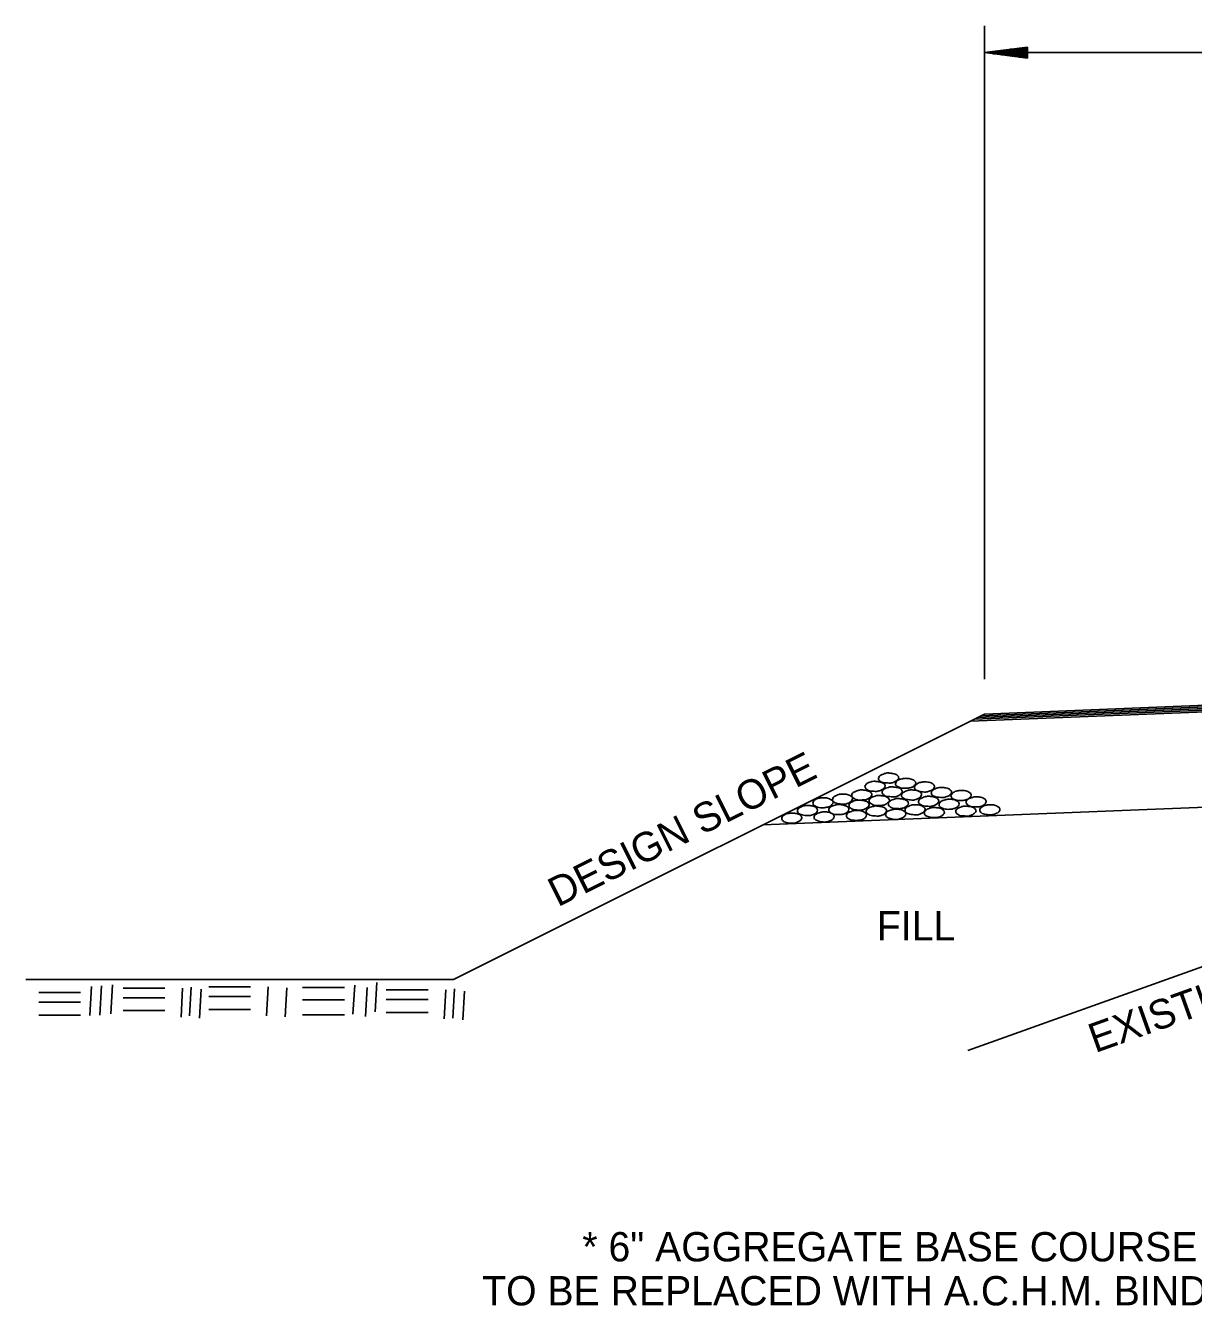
# Model space of a CAD drawing. Extents: x 836 to 5683, y -463 to 1545.
# Drawn here: x 4460.8 to 4699.8, y 626.9 to 890.5 of the extents above; entities that cross this region are included whole.
import ezdxf

# ---------------------------------------------------------------- set-up
doc = ezdxf.new("R2010")
doc.units = 0
doc.layers.add('R_Grid', color=7, linetype='Continuous')
doc.layers.add('R_No Plot', color=7, linetype='Continuous')

msp = doc.modelspace()

# ---------------------------------------------------------------- linework, layer by layer
at = {"layer": 'R_Grid'}
for p, q in [((4657.04, 756.76), (4657.04, 890.46)), ((4665.86, 886.11), (4657.04, 884.96)), ((4665.87, 885.88), (4664.13, 885.87)), ((4665.86, 886.11), (4665.87, 883.82)), ((4657.04, 884.96), (5217.98, 884.96)), ((4657.04, 884.96), (4665.87, 884.96)), ((4665.87, 883.82), (4657.04, 884.96)), ((4665.86, 885.19), (4658.83, 885.19)), ((4665.87, 884.74), (4658.84, 884.73)), ((4665.87, 885.42), (4660.56, 885.41)), ((4665.87, 884.5), (4660.57, 884.5)), ((4665.86, 885.65), (4662.34, 885.65)), ((4665.87, 884.28), (4662.35, 884.27)), ((4665.87, 884.04), (4664.14, 884.04))]:
    msp.add_line(p, q, dxfattribs=at)
at = {"layer": 'R_No Plot'}
for p, q in [((4654.18, 748.2), (5220.52, 770.79)), ((4654.91, 748.58), (5219.89, 771.11)), ((4655.64, 748.93), (5219.26, 771.42)), ((4656.39, 749.31), (5218.6, 771.74)), ((4657.04, 749.63), (5218, 772.04)), ((4548.38, 695.34), (4657.04, 749.63)), ((4611.68, 726.96), (4831.44, 735.71)), ((4782.86, 727.01), (4653.67, 680.84)), ((4460.81, 695.34), (4548.38, 695.34)), ((4474.27, 693.88), (4473.92, 687.95)), ((4476.29, 694.02), (4475.98, 688.07)), ((4478.57, 694.22), (4478.21, 688.31)), ((4480.72, 693.57), (4489.3, 693.57)), ((4492.91, 693.57), (4492.59, 687.64)), ((4494.7, 693.76), (4494.36, 687.87)), ((4496.73, 693.38), (4496.4, 687.43)), ((4498.26, 693.83), (4506.84, 693.83)), ((4510.46, 693.83), (4510.12, 687.91)), ((4514.25, 693.6), (4513.93, 687.7)), ((4517.45, 693.69), (4526.02, 693.69)), ((4528.14, 694.18), (4527.79, 688.26)), ((4530.68, 693.67), (4530.33, 687.78)), ((4532.69, 694.71), (4532.34, 688.75)), ((4548.58, 693.4), (4548.25, 687.45)), ((4463.46, 692.68), (4472.01, 692.68)), ((4463.46, 690.71), (4472.01, 690.71)), ((4480.72, 691.61), (4489.3, 691.61)), ((4498.26, 691.85), (4506.84, 691.85)), ((4517.45, 691.16), (4526.02, 691.16)), ((4534.6, 693.19), (4543.19, 693.19)), ((4534.6, 691.22), (4543.19, 691.22)), ((4546.79, 693.19), (4546.48, 687.27)), ((4550.61, 692.96), (4550.26, 687.06)), ((4463.46, 688.05), (4472.01, 688.05)), ((4480.72, 688.97), (4489.3, 688.97)), ((4498.26, 689.22), (4506.84, 689.22)), ((4517.45, 688.11), (4526.02, 688.11)), ((4534.6, 688.57), (4543.19, 688.57))]:
    msp.add_line(p, q, dxfattribs=at)
for points in [[(4634.61, 735.9), (4635.35, 735.8), (4636.19, 735.59), (4636.66, 735.18), (4636.73, 734.93), (4636.5, 734.48), (4636.23, 734.29), (4635.74, 734.03), (4635.04, 733.83), (4634.69, 733.83), (4634.15, 733.89), (4633.53, 733.93), (4633.08, 734.12), (4632.67, 734.52), (4632.59, 734.79), (4632.74, 735.19), (4633.07, 735.47), (4633.38, 735.61), (4633.86, 735.77), (4634.15, 735.87), (4634.61, 735.9)], [(4637.38, 737.59), (4638.1, 737.5), (4638.97, 737.26), (4639.43, 736.87), (4639.5, 736.61), (4639.28, 736.17), (4639, 735.97), (4638.5, 735.69), (4637.82, 735.52), (4637.45, 735.52), (4636.92, 735.58), (4636.29, 735.61), (4635.86, 735.8), (4635.43, 736.2), (4635.37, 736.47), (4635.5, 736.88), (4635.82, 737.13), (4636.13, 737.28), (4636.62, 737.45), (4636.9, 737.57), (4637.38, 737.59)], [(4640.88, 736.5), (4641.62, 736.44), (4642.48, 736.16), (4642.9, 735.78), (4642.97, 735.56), (4642.75, 735.08), (4642.54, 734.86), (4642.03, 734.61), (4641.36, 734.47), (4640.98, 734.45), (4640.44, 734.46), (4639.82, 734.56), (4639.38, 734.77), (4638.92, 735.11), (4638.85, 735.4), (4638.97, 735.78), (4639.33, 736.1), (4639.63, 736.24), (4640.13, 736.38), (4640.43, 736.44), (4640.88, 736.5)], [(4644.74, 735.75), (4645.46, 735.73), (4646.36, 735.44), (4646.77, 735.02), (4646.85, 734.77), (4646.6, 734.32), (4646.37, 734.12), (4645.89, 733.91), (4645.18, 733.71), (4644.8, 733.68), (4644.26, 733.73), (4643.67, 733.83), (4643.21, 734.01), (4642.78, 734.36), (4642.71, 734.63), (4642.85, 735.03), (4643.18, 735.29), (4643.48, 735.52), (4643.97, 735.67), (4644.28, 735.73), (4644.74, 735.75)], [(4627.99, 733.27), (4628.74, 733.22), (4629.58, 732.95), (4630.02, 732.54), (4630.06, 732.29), (4629.85, 731.86), (4629.62, 731.65), (4629.14, 731.4), (4628.44, 731.21), (4628.08, 731.21), (4627.53, 731.27), (4626.94, 731.32), (4626.47, 731.49), (4626.02, 731.88), (4625.96, 732.17), (4626.08, 732.56), (4626.41, 732.82), (4626.73, 733.01), (4627.25, 733.18), (4627.53, 733.25), (4627.99, 733.27)], [(4631.91, 734.12), (4632.64, 734.05), (4633.49, 733.78), (4633.94, 733.42), (4634, 733.15), (4633.76, 732.72), (4633.5, 732.48), (4633.06, 732.22), (4632.36, 732.07), (4632, 732.07), (4631.44, 732.05), (4630.83, 732.15), (4630.36, 732.36), (4629.93, 732.75), (4629.88, 732.99), (4630.01, 733.43), (4630.32, 733.68), (4630.66, 733.83), (4631.17, 733.99), (4631.44, 734.08), (4631.91, 734.12)], [(4635.44, 732.99), (4636.18, 732.92), (4637.06, 732.66), (4637.5, 732.27), (4637.58, 732.02), (4637.35, 731.57), (4637.11, 731.38), (4636.59, 731.08), (4635.92, 730.93), (4635.54, 730.93), (4634.99, 730.95), (4634.39, 731.01), (4633.94, 731.25), (4633.5, 731.61), (4633.44, 731.9), (4633.58, 732.29), (4633.91, 732.56), (4634.23, 732.7), (4634.69, 732.85), (4634.98, 732.95), (4635.44, 732.99)], [(4638.13, 734.76), (4638.85, 734.67), (4639.73, 734.46), (4640.15, 734.03), (4640.21, 733.79), (4640, 733.34), (4639.74, 733.14), (4639.28, 732.87), (4638.59, 732.7), (4638.21, 732.7), (4637.66, 732.75), (4637.05, 732.78), (4636.6, 732.99), (4636.17, 733.38), (4636.09, 733.65), (4636.22, 734.06), (4636.56, 734.31), (4636.89, 734.46), (4637.38, 734.64), (4637.66, 734.74), (4638.13, 734.76)], [(4642.1, 734.11), (4642.83, 734.08), (4643.72, 733.81), (4644.13, 733.39), (4644.19, 733.14), (4643.97, 732.69), (4643.76, 732.49), (4643.24, 732.25), (4642.57, 732.05), (4642.2, 732.05), (4641.63, 732.09), (4641.04, 732.19), (4640.59, 732.35), (4640.14, 732.73), (4640.08, 733.01), (4640.19, 733.42), (4640.54, 733.67), (4640.86, 733.84), (4641.35, 734.03), (4641.63, 734.1), (4642.1, 734.11)], [(4648.2, 734.62), (4648.95, 734.58), (4649.8, 734.31), (4650.22, 733.91), (4650.3, 733.64), (4650.06, 733.21), (4649.87, 733.01), (4649.35, 732.78), (4648.66, 732.56), (4648.3, 732.56), (4647.75, 732.61), (4647.17, 732.68), (4646.68, 732.85), (4646.22, 733.23), (4646.16, 733.5), (4646.29, 733.91), (4646.62, 734.17), (4646.96, 734.36), (4647.45, 734.54), (4647.75, 734.59), (4648.2, 734.62)], [(4652.26, 734.01), (4652.99, 733.99), (4653.83, 733.68), (4654.26, 733.31), (4654.33, 733.05), (4654.12, 732.58), (4653.87, 732.39), (4653.4, 732.15), (4652.69, 731.96), (4652.33, 731.93), (4651.79, 731.98), (4651.18, 732.07), (4650.71, 732.25), (4650.27, 732.61), (4650.2, 732.89), (4650.34, 733.28), (4650.66, 733.57), (4651, 733.77), (4651.49, 733.91), (4651.8, 733.99), (4652.26, 734.01)], [(4620.81, 730.93), (4621.53, 730.89), (4622.41, 730.64), (4622.83, 730.21), (4622.9, 729.97), (4622.68, 729.51), (4622.45, 729.31), (4621.96, 729.1), (4621.27, 728.88), (4620.9, 728.88), (4620.33, 728.92), (4619.73, 729.02), (4619.28, 729.17), (4618.84, 729.55), (4618.78, 729.84), (4618.9, 730.23), (4619.25, 730.5), (4619.58, 730.69), (4620.06, 730.85), (4620.33, 730.92), (4620.81, 730.93)], [(4623.97, 732.53), (4624.7, 732.49), (4625.55, 732.19), (4626, 731.83), (4626.07, 731.6), (4625.82, 731.12), (4625.61, 730.88), (4625.1, 730.67), (4624.43, 730.5), (4624.08, 730.47), (4623.5, 730.48), (4622.87, 730.6), (4622.44, 730.8), (4622, 731.15), (4621.94, 731.42), (4622.07, 731.83), (4622.39, 732.12), (4622.73, 732.27), (4623.21, 732.43), (4623.49, 732.49), (4623.97, 732.53)], [(4627.28, 731.15), (4627.98, 731.07), (4628.82, 730.8), (4629.26, 730.43), (4629.31, 730.17), (4629.12, 729.73), (4628.88, 729.48), (4628.4, 729.24), (4627.68, 729.1), (4627.32, 729.1), (4626.76, 729.11), (4626.16, 729.17), (4625.7, 729.38), (4625.27, 729.77), (4625.18, 730.05), (4625.32, 730.45), (4625.64, 730.7), (4625.99, 730.84), (4626.48, 731), (4626.78, 731.1), (4627.28, 731.15)], [(4631.35, 732.04), (4632.06, 731.99), (4632.95, 731.74), (4633.38, 731.32), (4633.44, 731.07), (4633.22, 730.63), (4633, 730.43), (4632.49, 730.18), (4631.82, 729.99), (4631.42, 729.99), (4630.87, 730.02), (4630.27, 730.11), (4629.82, 730.28), (4629.38, 730.67), (4629.31, 730.93), (4629.45, 731.34), (4629.78, 731.6), (4630.1, 731.78), (4630.59, 731.96), (4630.87, 732.02), (4631.35, 732.04)], [(4634.93, 730.84), (4635.65, 730.76), (4636.5, 730.5), (4636.92, 730.11), (4636.99, 729.88), (4636.79, 729.43), (4636.56, 729.19), (4636.07, 728.93), (4635.37, 728.78), (4634.99, 728.78), (4634.44, 728.8), (4633.86, 728.87), (4633.38, 729.1), (4632.92, 729.46), (4632.85, 729.76), (4633, 730.14), (4633.34, 730.41), (4633.66, 730.56), (4634.15, 730.7), (4634.46, 730.8), (4634.93, 730.84)], [(4639.41, 732.36), (4640.14, 732.27), (4640.98, 732.04), (4641.42, 731.63), (4641.48, 731.38), (4641.25, 730.93), (4641.04, 730.73), (4640.54, 730.47), (4639.86, 730.29), (4639.48, 730.29), (4638.94, 730.33), (4638.32, 730.38), (4637.85, 730.6), (4637.43, 730.98), (4637.36, 731.26), (4637.47, 731.64), (4637.81, 731.9), (4638.15, 732.07), (4638.66, 732.23), (4638.94, 732.34), (4639.41, 732.36)], [(4642.84, 731.1), (4643.57, 731.04), (4644.43, 730.76), (4644.84, 730.37), (4644.91, 730.11), (4644.68, 729.67), (4644.49, 729.47), (4643.99, 729.25), (4643.29, 729.02), (4642.92, 729.02), (4642.37, 729.09), (4641.77, 729.15), (4641.31, 729.31), (4640.84, 729.71), (4640.79, 729.99), (4640.92, 730.38), (4641.25, 730.65), (4641.59, 730.81), (4642.07, 731), (4642.37, 731.07), (4642.84, 731.1)], [(4645.63, 732.82), (4646.37, 732.76), (4647.2, 732.49), (4647.63, 732.1), (4647.69, 731.88), (4647.49, 731.39), (4647.25, 731.19), (4646.75, 730.92), (4646.05, 730.76), (4645.7, 730.76), (4645.16, 730.77), (4644.55, 730.84), (4644.08, 731.07), (4643.62, 731.43), (4643.55, 731.74), (4643.7, 732.12), (4644.03, 732.39), (4644.35, 732.53), (4644.84, 732.69), (4645.18, 732.79), (4645.63, 732.82)], [(4646.75, 730.5), (4647.48, 730.47), (4648.36, 730.2), (4648.78, 729.78), (4648.85, 729.53), (4648.63, 729.1), (4648.42, 728.89), (4647.91, 728.64), (4647.23, 728.46), (4646.85, 728.46), (4646.29, 728.5), (4645.68, 728.59), (4645.25, 728.74), (4644.79, 729.13), (4644.73, 729.41), (4644.86, 729.8), (4645.2, 730.06), (4645.51, 730.24), (4646, 730.44), (4646.29, 730.5), (4646.75, 730.5)], [(4649.79, 732.22), (4650.51, 732.18), (4651.38, 731.88), (4651.81, 731.51), (4651.87, 731.28), (4651.65, 730.79), (4651.44, 730.57), (4650.92, 730.34), (4650.24, 730.18), (4649.88, 730.15), (4649.33, 730.16), (4648.71, 730.27), (4648.27, 730.48), (4647.83, 730.81), (4647.75, 731.12), (4647.89, 731.51), (4648.2, 731.81), (4648.55, 731.95), (4649.03, 732.1), (4649.32, 732.18), (4649.79, 732.22)], [(4653.17, 730.81), (4653.94, 730.74), (4654.79, 730.52), (4655.24, 730.1), (4655.32, 729.87), (4655.09, 729.41), (4654.84, 729.21), (4654.32, 728.93), (4653.65, 728.76), (4653.29, 728.76), (4652.73, 728.81), (4652.11, 728.84), (4651.66, 729.07), (4651.25, 729.45), (4651.18, 729.73), (4651.31, 730.11), (4651.64, 730.38), (4651.94, 730.53), (4652.44, 730.7), (4652.73, 730.81), (4653.17, 730.81)], [(4655.37, 732.73), (4656.1, 732.65), (4656.94, 732.39), (4657.36, 731.99), (4657.42, 731.76), (4657.22, 731.3), (4656.99, 731.07), (4656.49, 730.8), (4655.78, 730.67), (4655.43, 730.67), (4654.89, 730.69), (4654.28, 730.73), (4653.8, 730.96), (4653.36, 731.34), (4653.3, 731.61), (4653.42, 732.02), (4653.76, 732.28), (4654.09, 732.43), (4654.57, 732.58), (4654.91, 732.68), (4655.37, 732.73)], [(4658.15, 731.08), (4658.87, 731.06), (4659.73, 730.75), (4660.14, 730.38), (4660.22, 730.13), (4660.01, 729.66), (4659.76, 729.46), (4659.31, 729.24), (4658.58, 729.05), (4658.23, 729.02), (4657.69, 729.07), (4657.07, 729.17), (4656.6, 729.33), (4656.16, 729.7), (4656.1, 729.97), (4656.23, 730.37), (4656.55, 730.67), (4656.89, 730.84), (4657.39, 731), (4657.69, 731.06), (4658.15, 731.08)], [(4617.57, 729.38), (4618.34, 729.31), (4619.18, 729.07), (4619.6, 728.64), (4619.67, 728.42), (4619.45, 727.96), (4619.24, 727.77), (4618.73, 727.53), (4618.04, 727.31), (4617.67, 727.31), (4617.12, 727.35), (4616.53, 727.42), (4616.07, 727.62), (4615.62, 727.98), (4615.55, 728.27), (4615.69, 728.66), (4616, 728.93), (4616.33, 729.13), (4616.84, 729.29), (4617.12, 729.35), (4617.57, 729.38)], [(4624.23, 729.63), (4624.95, 729.6), (4625.8, 729.29), (4626.21, 728.92), (4626.3, 728.66), (4626.08, 728.19), (4625.85, 727.98), (4625.39, 727.77), (4624.67, 727.58), (4624.3, 727.54), (4623.75, 727.61), (4623.16, 727.71), (4622.68, 727.9), (4622.23, 728.23), (4622.17, 728.51), (4622.29, 728.9), (4622.64, 729.19), (4622.96, 729.38), (4623.44, 729.52), (4623.77, 729.6), (4624.23, 729.63)], [(4630.81, 729.93), (4631.54, 729.88), (4632.43, 729.58), (4632.84, 729.22), (4632.9, 729), (4632.68, 728.51), (4632.47, 728.27), (4631.95, 728.03), (4631.27, 727.91), (4630.91, 727.88), (4630.36, 727.9), (4629.73, 727.98), (4629.29, 728.19), (4628.85, 728.55), (4628.78, 728.82), (4628.92, 729.22), (4629.24, 729.51), (4629.58, 729.66), (4630.04, 729.81), (4630.35, 729.88), (4630.81, 729.93)], [(4638.88, 730.15), (4639.58, 730.13), (4640.47, 729.84), (4640.88, 729.46), (4640.96, 729.21), (4640.74, 728.73), (4640.5, 728.55), (4640.04, 728.32), (4639.33, 728.1), (4638.95, 728.07), (4638.39, 728.13), (4637.81, 728.24), (4637.33, 728.43), (4636.89, 728.76), (4636.82, 729.05), (4636.96, 729.45), (4637.3, 729.75), (4637.62, 729.93), (4638.11, 730.06), (4638.4, 730.13), (4638.88, 730.15)]]:
    msp.add_spline(points, degree=3, dxfattribs=at)

# ---------------------------------------------------------------- texts
for s, rotation, p in [('DESIGN SLOPE', 26.565, (4569.72, 710.08)), ('EXISTING SLOPE', 19.6609, (4679.7, 680.25))]:
    msp.add_text(s, height=6, rotation=rotation, dxfattribs=at).set_placement(p)
for s, p in [('FILL', (4635.02, 703.32)), ('* 6" AGGREGATE BASE COURSE (CLASS 7)', (4574.74, 637.66)), ('TO BE REPLACED WITH A.C.H.M. BINDER COURSE (1")', (4554.23, 628.66))]:
    msp.add_text(s, height=6, dxfattribs=at).set_placement(p)

doc.saveas('drawing.dxf')
